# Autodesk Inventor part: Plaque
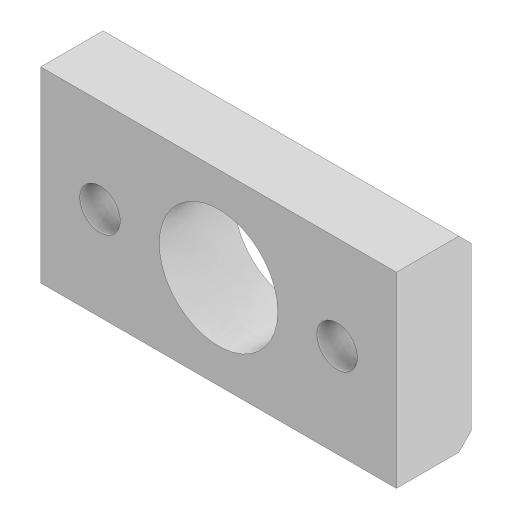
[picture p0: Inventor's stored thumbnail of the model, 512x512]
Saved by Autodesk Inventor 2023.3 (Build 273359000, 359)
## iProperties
Created: 2024-11
Part Number: Plaque
Material: Générique
Description: STEP AP203
Document SubType Name: Modeling
Designer: Thier
Density: 1 g/cm^3
Appearance: Par défaut
Title: Plaque.STEP
Revision Number: ANY
Sending System: SolidWorks 2017
Preprocessor: SwSTEP 2.0
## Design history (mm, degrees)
feature "Chanfrein1"
node "Solide1"
